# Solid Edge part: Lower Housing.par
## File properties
Accuracy: 0.99
Author: CADCIM
Template: NORMENG.PAR
Last saved by: TIET
Revision: 9
Application: Solid Edge
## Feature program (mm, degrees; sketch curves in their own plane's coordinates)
sketch for "unnamed Protrusion 1" plane through (0, 0, 0) normal (0, -1, 0) x-axis (1, 0, 0)
  line (0, 0) -> (-190.5, 0)
  line (-190.5, 0) -> (-190.5, -10.414)
  line (-190.5, -10.414) -> (-152.4, -10.414)
  arc centre (-0.1761, -3.0894) radius 152.4 from (-88.9, -127) to (-152.4, -10.414) cw
  line (-88.9, -127) -> (-177.8, -127)
  line (-177.8, -127) -> (-177.8, -165.1)
  line (-177.8, -165.1) -> (0, -165.1)
  line (177.8, -165.1) -> (0, -165.1)
  line (177.8, -127) -> (177.8, -165.1)
  line (88.9, -127) -> (177.8, -127)
  arc centre (0.1761, -3.0894) radius 152.4 from (88.9, -127) to (152.4, -10.414) ccw
  line (190.5, -10.414) -> (152.4, -10.414)
  line (190.5, 0) -> (190.5, -10.414)
  line (0, 0) -> (190.5, 0)
extrude "unnamed Protrusion 1" add finite 203.2 symmetric
sketch for "RevolvedCutout_1" plane through (0, 0, 0) normal (0, 0, 1) x-axis (0, 1, 0)
  line (-95.25, 0) -> (95.25, 0)
  line (95.25, 0) -> (95.25, 146.05)
  line (95.25, 146.05) -> (-95.25, 146.05)
  line (-95.25, 146.05) -> (-95.25, 0)
  dimension (linear) = 95.25
revolve "RevolvedCutout_1" cut finite 180 deg
sketch for "unnamed Cutout 1" plane through (0, -101.6, -82.55) normal (0, -1, 0) x-axis (1, 0, 0)
  arc centre (0, 82.55) radius 123.825 from (123.825, 82.55) to (-123.825, 82.55) cw
  line (-123.825, 82.55) -> (123.825, 82.55)
extrude "unnamed Cutout 1" cut through along -normal
sketch for "unnamed Cutout 2" plane through (0, 101.6, -82.55) normal (0, 1, 0) x-axis (-1, 0, 0)
  arc centre (0, 82.55) radius 38.1 from (38.1, 82.55) to (-38.1, 82.55) cw
  line (-38.1, 82.55) -> (38.1, 82.55)
extrude "unnamed Cutout 2" cut through along -normal
sketch for "Hole_1" plane through (114.3, 0, 0) normal (0, 0, 1) x-axis (0, 1, 0)
  hole centre (-76.2, -57.15) bore radius 5.207
hole "Hole_1" diameter 10.414 through
pattern "unnamed Pattern 1" of "Hole_1"
pattern "unnamed Pattern 2"
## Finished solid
Body 1: solid body, 28 faces, 70 edges, 36 vertices.
  Faces by surface: plane 15, cylinder 13
  Edges by curve: line 44, circle 26
Bounding box of the edges (mm): 381.000 x 203.200 x 165.100, from (-190.5, -101.6, -165.1) to (190.5, 101.6, 0).
Cylindrical faces by radius (mm): R5.207 x8, R38.1 x1, R123.825 x1, R146.05 x1, R152.4 x2
Planar faces by outward normal: +x 2, +y 2, +z 4, -x 2, -y 2, -z 3
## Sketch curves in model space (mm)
line (190.5, 0, 0) -> (190.5, 0, -10.414)
line (190.5, 0, -10.414) -> (152.4, 0, -10.414)
arc centre (0.1761, 0, -3.0894) radius 152.4 from (88.9, 0, -127) through (134.012, 0, -75.9848) to (152.4, 0, -10.414)
line (88.9, 0, -127) -> (177.8, 0, -127)
line (177.8, 0, -127) -> (177.8, 0, -165.1)
line (177.8, 0, -165.1) -> (0, 0, -165.1)
line (-177.8, 0, -165.1) -> (0, 0, -165.1)
line (-177.8, 0, -127) -> (-177.8, 0, -165.1)
line (-88.9, 0, -127) -> (-177.8, 0, -127)
arc centre (-0.1761, 0, -3.0894) radius 152.4 from (-88.9, 0, -127) through (-134.012, 0, -75.9848) to (-152.4, 0, -10.414)
line (-190.5, 0, -10.414) -> (-152.4, 0, -10.414)
line (-190.5, 0, 0) -> (-190.5, 0, -10.414)
line (0, 0, 0) -> (-190.5, 0, 0)
line (0, 0, 0) -> (190.5, 0, 0)
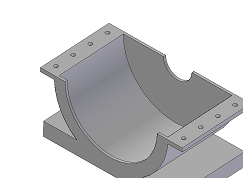
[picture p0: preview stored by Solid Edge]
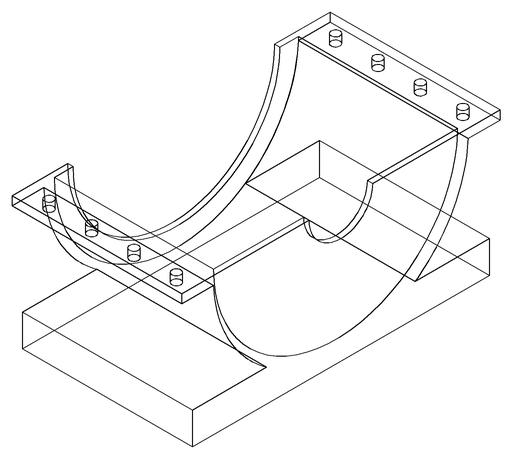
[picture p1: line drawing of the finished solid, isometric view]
